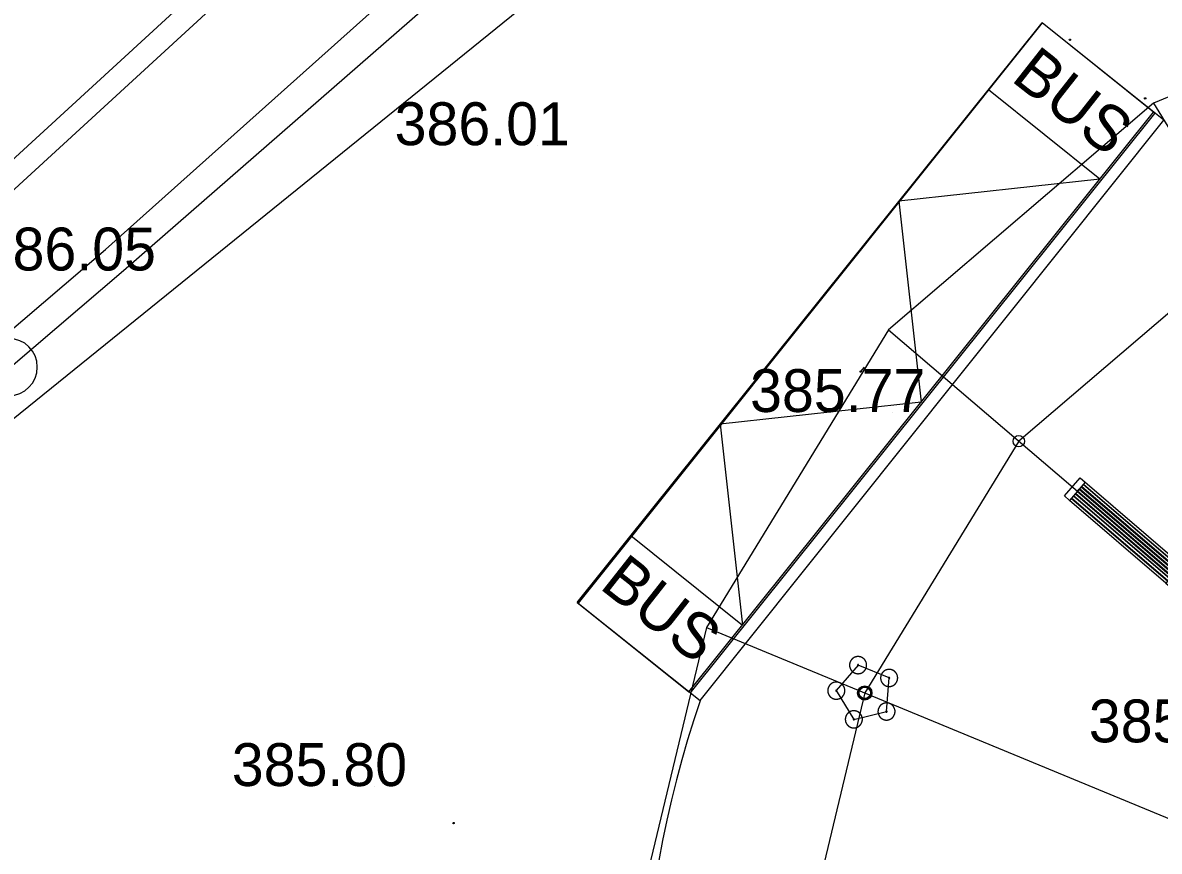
# Model space of a CAD drawing. Extents: x -438233 to -437334, y -1133133 to -1132623.
# Drawn here: x -438087.94 to -438068.05, y -1132948.37 to -1132933.88 of the extents above; entities that cross this region are included whole.
import ezdxf

# ---------------------------------------------------------------- set-up
doc = ezdxf.new("R2010")
doc.units = 0
for name, color, linetype in [('MOBILIÁŘ', 7, 'Continuous'), ('OSY', 7, 'Continuous'), ('SILNA 1', 7, 'Continuous'), ('SILNA 2', 7, 'Continuous'), ('TENKA', 7, 'Continuous'), ('urban islands', 7, 'Continuous'), ('Vrstva 1', 7, 'Continuous'), ('Vrstva 10', 7, 'Continuous'), ('Vrstva 22', 7, 'Continuous'), ('Vrstva 3', 7, 'Continuous'), ('Vrstva 52', 7, 'Continuous'), ('Vrstva 9', 7, 'Continuous')]:
    doc.layers.add(name, color=color, linetype=linetype)

# ---------------------------------------------------------------- blocks, each defined once
blk = doc.blocks.new('A$C32EE4163')
at = {"layer": 'SILNA 1'}
for radius in [1.25, 1.25, 1.13, 1.13]:
    blk.add_circle((0, 0), radius, dxfattribs=at)
blk = doc.blocks.new('A$C1C6D51B8')
at = {"layer": 'urban islands'}
for p, q in [((-23400, 4190), (-1200, 4190)), ((-1200, 3710), (-23400, 3710)), ((-23400, 3660), (-1200, 3660)), ((-23400, 3239), (-23400, 3300)), ((-23400, 3180), (-1200, 3180)), ((-22900, 3710), (-22900, 3660)), ((-22900, 3180), (-22900, 3130)), ((-22900, 2650), (-22900, 2600)), ((-22900, 2120), (-22900, 2070)), ((-22290, 3660), (-22290, 3710)), ((-22290, 3130), (-22290, 3180)), ((-21900, 3180), (-21900, 3130)), ((-21900, 2650), (-21900, 2600)), ((-21900, 2120), (-21900, 2070)), ((-19450, 3710), (-19450, 3660)), ((-19450, 3180), (-19450, 3130)), ((-19450, 2650), (-19450, 2600)), ((-19450, 2120), (-19450, 2070)), ((-18950, 3660), (-18950, 3710)), ((-18950, 3180), (-18950, 3130)), ((-18950, 2650), (-18950, 2600)), ((-18950, 2120), (-18950, 2070)), ((-14850, 3710), (-14850, 3660)), ((-14850, 3180), (-14850, 3130)), ((-14850, 2650), (-14850, 2600)), ((-14850, 2120), (-14850, 2070)), ((-14350, 3660), (-14350, 3710)), ((-14350, 3180), (-14350, 3130)), ((-14350, 2650), (-14350, 2600)), ((-14350, 2120), (-14350, 2070)), ((-10250, 3710), (-10250, 3660)), ((-10250, 3180), (-10250, 3130)), ((-10250, 2650), (-10250, 2600)), ((-10250, 2120), (-10250, 2070)), ((-9750, 3660), (-9750, 3710)), ((-9750, 3180), (-9750, 3130)), ((-9750, 2650), (-9750, 2600)), ((-9750, 2120), (-9750, 2070)), ((-5650, 3710), (-5650, 3660)), ((-5650, 3180), (-5650, 3130)), ((-5650, 2650), (-5650, 2600)), ((-5650, 2120), (-5650, 2070)), ((-5150, 3660), (-5150, 3710)), ((-5150, 3180), (-5150, 3130)), ((-5150, 2650), (-5150, 2600)), ((-5150, 2120), (-5150, 2070)), ((-2700, 3130), (-2700, 3180)), ((-2700, 2600), (-2700, 2650)), ((-2700, 2070), (-2700, 2120)), ((-2310, 3710), (-2310, 3660)), ((-2310, 3180), (-2310, 3130)), ((-2300, 3710), (-2300, 3660)), ((-1700, 3710), (-1700, 3660)), ((-1700, 3180), (-1700, 3130)), ((-1700, 2650), (-1700, 2600)), ((-1700, 2120), (-1700, 2070)), ((-1200, 3214), (-1200, 3200)), ((-23400, 976), (-23400, 978)), ((-23400, 815), (-23400, 911)), ((-23400, 530), (-1200, 530)), ((-23400, 480), (-1200, 480)), ((-22900, 1590), (-22900, 1540)), ((-22900, 1060), (-22900, 1010)), ((-22900, 480), (-22900, 530)), ((-22290, 1010), (-22290, 1060)), ((-22290, 530), (-22290, 480)), ((-21900, 1590), (-21900, 1540)), ((-21900, 1060), (-21900, 1010)), ((-19450, 1590), (-19450, 1540)), ((-19450, 1060), (-19450, 1010)), ((-19450, 530), (-19450, 480)), ((-18950, 1590), (-18950, 1540)), ((-18950, 1060), (-18950, 1010)), ((-18950, 480), (-18950, 530)), ((-14850, 1590), (-14850, 1540)), ((-14850, 1060), (-14850, 1010)), ((-14850, 530), (-14850, 480)), ((-14350, 1590), (-14350, 1540)), ((-14350, 1060), (-14350, 1010)), ((-14350, 480), (-14350, 530)), ((-10250, 1590), (-10250, 1540)), ((-10250, 1060), (-10250, 1010)), ((-10250, 530), (-10250, 480)), ((-9750, 1590), (-9750, 1540)), ((-9750, 1060), (-9750, 1010)), ((-9750, 480), (-9750, 530)), ((-5650, 1590), (-5650, 1540)), ((-5650, 1060), (-5650, 1010)), ((-5650, 530), (-5650, 480)), ((-5150, 1590), (-5150, 1540)), ((-5150, 1060), (-5150, 1010)), ((-5150, 480), (-5150, 530)), ((-2700, 1540), (-2700, 1590)), ((-2700, 1010), (-2700, 1060)), ((-2310, 1060), (-2310, 1010)), ((-2310, 480), (-2310, 530)), ((-2300, 530), (-2300, 480)), ((-1700, 1590), (-1700, 1540)), ((-1700, 1060), (-1700, 1010)), ((-1700, 530), (-1700, 480)), ((-1200, 890), (-1200, 951))]:
    blk.add_line(p, q, dxfattribs=at)
for points in [[(-1200, 0), (-1200, 4190), (0, 4190), (0, 0), (-23400, 0), (-23400, 4190), (-24600, 4190), (-24600, 0), (-23400, 0)], [(-23400, 3130), (-1200, 3130), (-1200, 2650), (-23400, 2650)], [(-2505, 3165), (-2531, 3180)], [(-2479, 3180), (-2505, 3165)], [(-1200, 3375), (-1200, 3279), (-1200, 3440)], [(-1200, 3241), (-1200, 3180), (-1200, 3241)], [(-1200, 1060), (-23400, 1060), (-23400, 1540), (-1200, 1540)], [(-23400, 949), (-23400, 1010), (-1200, 1010)], [(-2531, 1010), (-2505, 1025)], [(-2505, 1025), (-2479, 1010)]]:
    blk.add_lwpolyline(points, dxfattribs=at)
for points in [[(-1200, 2120), (-23400, 2120), (-23400, 2600), (-1200, 2600)], [(-23400, 2070), (-1200, 2070), (-1200, 1590), (-23400, 1590)]]:
    blk.add_lwpolyline(points, close=True, dxfattribs=at)
for centre, radius, start, end in [((-2505, 3240), 80, 228.59038, 311.40962), ((-2505, 3243), 67.7, 247.84515, 292.15485), ((-2505, 950), 80, 48.59038, 131.40962), ((-2505, 947), 67.7, 67.84515, 112.15485)]:
    blk.add_arc(centre, radius, start, end, dxfattribs=at)
blk = doc.blocks.new('A$C7A6F5A01')
at = {"layer": 'Vrstva 1'}
for p, q in [((-20, 32), (-39, 0)), ((-39, 0), (-20, -35)), ((18, 32), (-20, 32)), ((40, 0), (18, 32)), ((18, -35), (40, 0)), ((-20, -35), (18, -35))]:
    blk.add_line(p, q, dxfattribs=at)
for points in [[(1497, 0), (1491, 133), (1481, 203), (1479, 219), (1476, 236), (1474, 253), (1471, 269), (1468, 286), (1465, 302), (1461, 319), (1458, 335), (1454, 351), (1450, 367), (1446, 383), (1442, 399), (1437, 415), (1432, 431), (1428, 447), (1423, 463), (1418, 478), (1412, 494), (1407, 509), (1401, 524), (1396, 540), (1390, 555), (1383, 570), (1377, 585), (1371, 600), (1364, 615), (1358, 630), (1351, 644), (1344, 659), (1336, 673), (1329, 688), (1322, 702), (1314, 716), (1306, 730), (1298, 744), (1290, 758), (1282, 772), (1274, 786), (1265, 799), (1256, 813), (1248, 826), (1239, 840), (1229, 853), (1220, 866), (1211, 879), (1201, 892), (1192, 905), (1182, 917), (1172, 930), (1162, 942), (1152, 955), (1142, 967), (1131, 979), (1121, 991), (1110, 1003), (1099, 1015), (1088, 1026), (1077, 1038), (1066, 1049), (1055, 1061), (1044, 1072), (1032, 1083), (1020, 1094), (1009, 1105), (997, 1115), (985, 1126), (973, 1136), (961, 1147), (948, 1157), (936, 1167), (923, 1177), (911, 1186), (898, 1196), (885, 1206), (872, 1215), (859, 1224), (846, 1233), (833, 1242), (819, 1251), (806, 1260), (792, 1268), (779, 1277), (765, 1285), (751, 1293), (737, 1301), (723, 1309), (709, 1317), (695, 1324), (681, 1332), (666, 1339), (652, 1346), (637, 1353), (623, 1360), (608, 1366), (593, 1373), (578, 1379), (563, 1385), (548, 1391), (533, 1397), (518, 1403), (503, 1409), (487, 1414), (472, 1419), (456, 1424), (441, 1429), (425, 1434), (409, 1438), (394, 1443), (378, 1447), (362, 1451), (346, 1455), (330, 1459), (314, 1462), (298, 1466), (281, 1469), (265, 1472), (249, 1475), (232, 1478), (216, 1480), (200, 1482), (183, 1485), (166, 1487), (150, 1488), (133, 1490), (116, 1491), (99, 1493), (83, 1494), (66, 1495), (-67, 1495), (-85, 1494), (-102, 1493), (-120, 1491), (-137, 1490), (-154, 1488), (-172, 1486), (-189, 1484), (-206, 1482), (-223, 1479), (-240, 1477), (-257, 1474), (-274, 1471), (-290, 1467), (-307, 1464), (-324, 1460), (-341, 1457), (-357, 1453), (-374, 1448), (-390, 1444), (-406, 1440), (-422, 1435), (-439, 1430), (-455, 1425), (-471, 1420), (-487, 1414), (-503, 1409), (-518, 1403), (-534, 1397), (-550, 1391), (-565, 1385), (-581, 1378), (-596, 1372), (-611, 1365), (-626, 1358), (-642, 1351), (-657, 1344), (-671, 1336), (-686, 1329), (-701, 1321), (-716, 1313), (-730, 1305), (-744, 1297), (-759, 1289), (-773, 1280), (-787, 1272), (-801, 1263), (-815, 1254), (-829, 1245), (-843, 1236), (-856, 1226), (-870, 1217), (-883, 1207), (-896, 1197), (-909, 1187), (-922, 1177), (-935, 1167), (-948, 1156), (-961, 1146), (-973, 1135), (-986, 1124), (-998, 1114), (-1010, 1102), (-1023, 1091), (-1035, 1080), (-1046, 1069), (-1058, 1057), (-1070, 1045), (-1081, 1033), (-1092, 1021), (-1104, 1009), (-1115, 997), (-1126, 985), (-1136, 972), (-1147, 960), (-1158, 947), (-1168, 934), (-1178, 921), (-1188, 908), (-1198, 895), (-1208, 882), (-1218, 869), (-1227, 855), (-1237, 841), (-1246, 828), (-1255, 814), (-1264, 800), (-1273, 786), (-1281, 772), (-1290, 758), (-1298, 743), (-1306, 729), (-1314, 714), (-1322, 700), (-1330, 685), (-1338, 670), (-1345, 655), (-1352, 640), (-1359, 625), (-1366, 610), (-1373, 594), (-1379, 579), (-1386, 564), (-1392, 548), (-1398, 532), (-1404, 517), (-1410, 501), (-1415, 485), (-1420, 469), (-1426, 453), (-1431, 437), (-1435, 420), (-1440, 404), (-1445, 388), (-1449, 371), (-1453, 355), (-1457, 338), (-1461, 321), (-1464, 304), (-1467, 288), (-1471, 271), (-1474, 254), (-1476, 237), (-1479, 220), (-1481, 202), (-1484, 185), (-1486, 168), (-1487, 150), (-1489, 133), (-1495, 67), (-1495, -66), (-1489, -136), (-1488, -153), (-1486, -170), (-1484, -186), (-1482, -203), (-1479, -220), (-1477, -236), (-1474, -253), (-1472, -269), (-1469, -285), (-1465, -302), (-1462, -318), (-1458, -334), (-1455, -350), (-1451, -366), (-1447, -382), (-1442, -398), (-1438, -414), (-1433, -429), (-1429, -445), (-1424, -461), (-1419, -476), (-1413, -492), (-1408, -507), (-1402, -522), (-1397, -537), (-1391, -552), (-1385, -568), (-1378, -582), (-1372, -597), (-1366, -612), (-1359, -627), (-1352, -641), (-1345, -656), (-1338, -670), (-1330, -685), (-1323, -699), (-1315, -713), (-1308, -727), (-1300, -741), (-1292, -755), (-1283, -769), (-1275, -783), (-1267, -796), (-1258, -810), (-1249, -823), (-1240, -837), (-1231, -850), (-1222, -863), (-1213, -876), (-1203, -889), (-1193, -902), (-1184, -914), (-1174, -927), (-1164, -939), (-1154, -952), (-1143, -964), (-1133, -976), (-1122, -988), (-1112, -1000), (-1101, -1012), (-1090, -1024), (-1079, -1035), (-1068, -1047), (-1057, -1058), (-1045, -1069), (-1034, -1080), (-1022, -1091), (-1010, -1102), (-999, -1113), (-987, -1124), (-974, -1134), (-962, -1145), (-950, -1155), (-938, -1165), (-925, -1175), (-912, -1185), (-900, -1194), (-887, -1204), (-874, -1213), (-861, -1223), (-848, -1232), (-834, -1241), (-821, -1250), (-808, -1259), (-794, -1267), (-780, -1276), (-767, -1284), (-753, -1292), (-739, -1300), (-725, -1308), (-711, -1316), (-696, -1324), (-682, -1331), (-668, -1338), (-653, -1346), (-639, -1353), (-624, -1360), (-609, -1366), (-595, -1373), (-580, -1379), (-565, -1385), (-550, -1392), (-534, -1397), (-519, -1403), (-504, -1409), (-489, -1414), (-473, -1420), (-458, -1425), (-442, -1430), (-426, -1434), (-411, -1439), (-395, -1444), (-379, -1448), (-363, -1452), (-347, -1456), (-331, -1460), (-315, -1463), (-299, -1467), (-283, -1470), (-266, -1473), (-250, -1476), (-233, -1479), (-217, -1481), (-200, -1484), (-184, -1486), (-167, -1488), (-151, -1490), (-134, -1491), (-67, -1495), (-1, -1495), (17, -1495), (34, -1494), (51, -1494), (68, -1494), (85, -1493), (103, -1492), (120, -1491), (137, -1489), (154, -1488), (171, -1486), (188, -1484), (204, -1482), (221, -1480), (238, -1477), (255, -1474), (271, -1471), (288, -1468), (305, -1465), (321, -1461), (338, -1458), (354, -1454), (370, -1450), (387, -1446), (403, -1441), (419, -1436), (435, -1432), (451, -1427), (467, -1422), (483, -1416), (498, -1411), (514, -1405), (530, -1399), (545, -1393), (561, -1387), (576, -1381), (592, -1374), (607, -1367), (622, -1361), (637, -1354), (652, -1346), (667, -1339), (682, -1331), (697, -1324), (711, -1316), (726, -1308), (740, -1300), (755, -1291), (769, -1283), (783, -1274), (797, -1265), (811, -1257), (825, -1247), (839, -1238), (852, -1229), (866, -1219), (879, -1210), (893, -1200), (906, -1190), (919, -1180), (932, -1169), (945, -1159), (958, -1149), (970, -1138), (983, -1127), (995, -1116), (1008, -1105), (1020, -1094), (1032, -1082), (1044, -1071), (1056, -1059), (1067, -1048), (1079, -1036), (1090, -1024), (1102, -1012), (1113, -999), (1124, -987), (1135, -975), (1146, -962), (1156, -949), (1167, -936), (1177, -923), (1187, -910), (1197, -897), (1207, -884), (1217, -870), (1227, -857), (1236, -843), (1246, -830), (1255, -816), (1264, -802), (1273, -788), (1281, -773), (1290, -759), (1298, -745), (1307, -730), (1315, -716), (1323, -701), (1330, -686), (1338, -671), (1346, -656), (1353, -641), (1360, -626), (1367, -611), (1374, -595), (1380, -580), (1387, -564), (1393, -549), (1399, -533), (1405, -517), (1410, -501), (1416, -486), (1421, -469), (1427, -453), (1431, -437), (1436, -421), (1441, -405), (1445, -388), (1450, -372), (1454, -355), (1457, -338), (1461, -322), (1465, -305), (1468, -288), (1471, -271), (1474, -254), (1476, -237), (1479, -220), (1481, -203), (1491, -136), (1494, -66)], [(-1, -101), (18, -98), (37, -92), (39, -91), (41, -90), (43, -89), (45, -88), (47, -87), (49, -86), (51, -85), (53, -84), (55, -83), (57, -82), (58, -81), (60, -80), (62, -78), (63, -77), (65, -76), (67, -75), (68, -73), (70, -72), (71, -70), (73, -69), (74, -68), (75, -66), (77, -65), (78, -63), (79, -62), (80, -60), (82, -59), (83, -57), (84, -55), (85, -54), (86, -52), (87, -50), (88, -49), (89, -47), (90, -45), (90, -44), (91, -42), (92, -40), (93, -38), (94, -37), (94, -35), (95, -33), (95, -31), (96, -29), (97, -28), (97, -26), (98, -24), (98, -22), (98, -20), (99, -18), (99, -16), (99, -15), (100, -13), (100, -11), (100, -9), (100, -7), (100, -5), (100, -3), (100, -1), (100, 1), (100, 2), (100, 4), (100, 6), (100, 8), (100, 10), (100, 12), (99, 14), (99, 16), (99, 18), (98, 19), (98, 21), (98, 23), (97, 25), (97, 27), (96, 29), (95, 31), (95, 32), (94, 34), (94, 36), (93, 38), (92, 40), (91, 41), (91, 43), (90, 45), (89, 47), (88, 48), (87, 50), (86, 52), (85, 53), (84, 55), (83, 57), (82, 58), (81, 60), (79, 61), (78, 63), (77, 64), (76, 66), (74, 67), (73, 69), (71, 70), (70, 72), (69, 73), (67, 74), (66, 76), (64, 77), (62, 78), (61, 79), (59, 81), (57, 82), (56, 83), (54, 84), (52, 85), (50, 86), (48, 87), (46, 88), (44, 89), (42, 90), (40, 91), (38, 92), (36, 93), (34, 94), (32, 94), (30, 95), (27, 96), (25, 96), (23, 97), (21, 98), (18, 98), (-17, 98), (-19, 98), (-21, 97), (-23, 96), (-26, 96), (-28, 95), (-30, 94), (-32, 94), (-34, 93), (-36, 92), (-38, 91), (-40, 90), (-42, 89), (-44, 88), (-46, 87), (-48, 86), (-50, 85), (-52, 84), (-54, 83), (-55, 82), (-57, 81), (-59, 80), (-60, 78), (-62, 77), (-64, 76), (-65, 75), (-67, 73), (-68, 72), (-70, 71), (-71, 69), (-72, 68), (-74, 66), (-75, 65), (-76, 63), (-78, 62), (-79, 60), (-80, 59), (-81, 57), (-82, 56), (-83, 54), (-85, 52), (-86, 51), (-87, 49), (-87, 47), (-88, 46), (-89, 44), (-90, 42), (-91, 41), (-92, 39), (-92, 37), (-93, 35), (-94, 34), (-94, 32), (-95, 30), (-96, 28), (-96, 26), (-97, 25), (-97, 23), (-98, 21), (-98, 19), (-98, 17), (-99, 15), (-99, 13), (-99, 12), (-99, 10), (-100, 8), (-100, 6), (-100, 4), (-100, 2), (-100, 0), (-100, -2), (-100, -3), (-100, -5), (-100, -7), (-100, -9), (-99, -11), (-99, -13), (-99, -15), (-99, -17), (-98, -18), (-98, -20), (-98, -22), (-97, -24), (-97, -26), (-96, -28), (-96, -29), (-95, -31), (-94, -33), (-94, -35), (-93, -37), (-92, -38), (-92, -40), (-91, -42), (-90, -44), (-89, -45), (-88, -47), (-87, -49), (-86, -50), (-85, -52), (-84, -54), (-83, -55), (-82, -57), (-80, -58), (-79, -60), (-78, -62), (-77, -63), (-75, -65), (-74, -66), (-72, -68), (-71, -69), (-70, -71), (-68, -72), (-66, -73), (-65, -75), (-63, -76), (-61, -77), (-60, -79), (-58, -80), (-56, -81), (-54, -82), (-52, -83), (-50, -85), (-48, -86), (-46, -87), (-44, -88), (-42, -89), (-40, -90), (-38, -91), (-36, -92), (-17, -98)]]:
    blk.add_lwpolyline(points, close=True, dxfattribs=at)
blk = doc.blocks.new('A$C5CBC2F6B')
at = {"layer": 'DEFPOINTS'}
blk.add_lwpolyline([(0, 5), (-4.76, 1.55), (-2.94, -4.05), (2.94, -4.05), (4.76, 1.55)], close=True, dxfattribs=at)
at = {"layer": 'MOBILIÁŘ', "xscale": 0.001, "yscale": 0.001}
for p in [(0, 5), (-4.75, 1.55), (4.76, 1.55), (-2.94, -4.05), (2.94, -4.05)]:
    blk.add_blockref('A$C7A6F5A01', p, dxfattribs=at)

msp = doc.modelspace()

# ---------------------------------------------------------------- linework, layer by layer
at = {"layer": 'DEFPOINTS'}
msp.add_circle((-438057.962, -1132951.913), 10.2, dxfattribs=at)
at = {"layer": 'OSY'}
for p, q in [((-438068.157, -1132935.291), (-438063.19, -1132943.389)), ((-438072.795, -1132939.255), (-438065.568, -1132945.422)), ((-438075.98, -1132944.458), (-438067.202, -1132948.09))]:
    msp.add_line(p, q, dxfattribs=at)
for points in [[(-438050.507, -1132933.894), (-438056.44, -1132932.473), (-438062.522, -1132932.954), (-438068.157, -1132935.291), (-438072.795, -1132939.255), (-438075.98, -1132944.458), (-438077.402, -1132950.391), (-438076.921, -1132956.473), (-438074.584, -1132962.109), (-438070.62, -1132966.746), (-438065.417, -1132969.932), (-438059.484, -1132971.354), (-438053.402, -1132970.872), (-438047.766, -1132968.535), (-438043.129, -1132964.571), (-438039.943, -1132959.368), (-438038.521, -1132953.435), (-438039.002, -1132947.353), (-438041.339, -1132941.718), (-438045.304, -1132937.08)], [(-438056.674, -1132935.463), (-438061.82, -1132935.87), (-438066.589, -1132937.848), (-438070.513, -1132941.202), (-438073.208, -1132945.605), (-438074.411, -1132950.625), (-438074.004, -1132955.771), (-438072.027, -1132960.54), (-438068.673, -1132964.464), (-438064.27, -1132967.16), (-438059.25, -1132968.363), (-438054.103, -1132967.956), (-438049.335, -1132965.978), (-438045.411, -1132962.624), (-438042.715, -1132958.221), (-438041.512, -1132953.201), (-438041.919, -1132948.055), (-438043.897, -1132943.286), (-438047.251, -1132939.362), (-438051.654, -1132936.666)], [(-438056.674, -1132935.463), (-438061.82, -1132935.87), (-438066.589, -1132937.848), (-438070.513, -1132941.202), (-438073.208, -1132945.605), (-438074.411, -1132950.625), (-438074.004, -1132955.771), (-438072.027, -1132960.54), (-438068.673, -1132964.464), (-438064.27, -1132967.16), (-438059.25, -1132968.363), (-438054.103, -1132967.956), (-438049.335, -1132965.978), (-438045.411, -1132962.624), (-438042.715, -1132958.221), (-438041.512, -1132953.201), (-438041.919, -1132948.055), (-438043.897, -1132943.286), (-438047.251, -1132939.362), (-438051.654, -1132936.666)]]:
    msp.add_lwpolyline(points, close=True, dxfattribs=at)
at = {"layer": 'SILNA 1'}
for centre in [(-438070.513, -1132941.202), (-438070.513, -1132941.202), (-438073.208, -1132945.605), (-438073.208, -1132945.605)]:
    msp.add_circle(centre, 0.1, dxfattribs=at)
at = {"layer": 'SILNA 2'}
msp.add_lwpolyline([(-438076.091, -1132945.736), (-438067.972, -1132935.583), (-438070.106, -1132933.881), (-438078.226, -1132944.034)], close=True, dxfattribs=at)
at = {"layer": 'Vrstva 1'}
for p, q in [((-438090.373, -1132942.634), (-438074.748, -1132930.004)), ((-438078.239, -1132944.023), (-438070.106, -1132933.881)), ((-438068.156, -1132935.445), (-438070.106, -1132933.881)), ((-438069.094, -1132936.616), (-438071.045, -1132935.052)), ((-438076.289, -1132945.587), (-438068.156, -1132935.445)), ((-438076.263, -1132945.609), (-438068.13, -1132935.467)), ((-438078.935, -1132936.023), (-438078.935, -1132936.023)), ((-438086.179, -1132938.215), (-438086.179, -1132938.215)), ((-438072.715, -1132940.691), (-438072.715, -1132940.691)), ((-438077.301, -1132942.853), (-438075.35, -1132944.417)), ((-438078.239, -1132944.023), (-438076.289, -1132945.587)), ((-438081.785, -1132947.234), (-438081.785, -1132947.234))]:
    msp.add_line(p, q, dxfattribs=at)
for points in [[(-438069.094, -1132936.616), (-438072.609, -1132937.002), (-438072.222, -1132940.516), (-438075.737, -1132940.903), (-438075.35, -1132944.417)], [(-438073.278, -1132939.984), (-438073.214, -1132939.905)]]:
    msp.add_lwpolyline(points, dxfattribs=at)
for centre in [(-438069.618, -1132934.179), (-438068.301, -1132935.206), (-438073.278, -1132939.984), (-438080.404, -1132947.882)]:
    msp.add_circle(centre, 0.0127, dxfattribs=at)
for centre, radius, start, end in [((-438057.962, -1132951.913), 27.6, 21.7557, 127.458), ((-438057.961, -1132951.909), 19.15, 161.159, 229.4804)]:
    msp.add_arc(centre, radius, start, end, dxfattribs=at)
at = {"layer": 'Vrstva 10'}
msp.add_lwpolyline([(-438095.924, -1132946.534), (-438086.179, -1132938.215), (-438074.983, -1132928.454)], dxfattribs=at)
at = {"layer": 'Vrstva 22'}
msp.add_arc((-438088.188, -1132939.904), 0.5, 270, 90, dxfattribs=at)
at = {"layer": 'Vrstva 52'}
for points in [[(-438128.855, -1132990.779), (-438128.856, -1132990.91), (-438128.989, -1132990.91), (-438128.989, -1132990.659), (-438128.93, -1132990.596), (-438129.59, -1132987.39), (-438128.59, -1132984.69), (-438123.607, -1132978.703), (-438122.927, -1132977.811), (-438122.184, -1132976.902), (-438122.789, -1132976.078), (-438121.848, -1132973.845), (-438121.368, -1132972.611), (-438119.619, -1132967.617), (-438116.421, -1132963.158), (-438109.667, -1132956.824), (-438099.67, -1132947.487), (-438095.701, -1132943.378), (-438089.916, -1132937.924), (-438083.958, -1132932.455), (-438080.074, -1132928.641), (-438079.488, -1132927.786), (-438078.793, -1132926.015), (-438077.623, -1132919.546)], [(-438077.217, -1132919.546), (-438078.406, -1132926.125), (-438079.132, -1132927.975), (-438079.766, -1132928.899), (-438083.683, -1132932.745), (-438089.644, -1132938.217), (-438095.42, -1132943.663), (-438099.389, -1132947.772), (-438109.394, -1132957.116), (-438116.119, -1132963.423), (-438119.26, -1132967.803), (-438120.993, -1132972.75), (-438122.088, -1132975.591), (-438122.213, -1132976.074), (-438122.355, -1132976.074), (-438122.355, -1132975.945)]]:
    msp.add_lwpolyline(points, dxfattribs=at)
at = {"layer": 'Vrstva 9'}
msp.add_lwpolyline([(-438100.102, -1132946.562), (-438096.145, -1132946.087), (-438086.495, -1132937.848), (-438075.407, -1132927.936)], dxfattribs=at)

# ---------------------------------------------------------------- block references
at = {"layer": 'MOBILIÁŘ'}
for name, p, xscale, yscale, rotation in [('A$C1C6D51B8', (-438069.441, -1132941.842), 0.00010000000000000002, 0.0001, 139.36791051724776), ('A$C5CBC2F6B', (-438073.208, -1132945.605), 0.1, 0.10000000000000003, 13.523388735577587)]:
    msp.add_blockref(name, p, dxfattribs=dict(at, xscale=xscale, yscale=yscale, rotation=rotation))
at = {"layer": 'TENKA', "xscale": 0.1, "yscale": 0.10000000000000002}
msp.add_blockref('A$C32EE4163', (-438073.208, -1132945.605), dxfattribs=at)

# ---------------------------------------------------------------- texts
at = {"layer": 'Vrstva 1'}
for p in [(-438070.669, -1132934.883), (-438077.871, -1132943.763)]:
    msp.add_text('BUS', height=0.8, rotation=321.7793, dxfattribs=at).set_placement(p)
at = {"layer": 'Vrstva 3'}
for s, p in [('386.01 ', (-438081.435, -1132936.023)), ('386.05 ', (-438088.679, -1132938.215)), ('385.77 ', (-438075.215, -1132940.691)), ('385.56 ', (-438069.287, -1132946.47)), ('385.80 ', (-438084.285, -1132947.234))]:
    msp.add_text(s, height=0.75, dxfattribs=at).set_placement(p)

doc.saveas('drawing.dxf')
